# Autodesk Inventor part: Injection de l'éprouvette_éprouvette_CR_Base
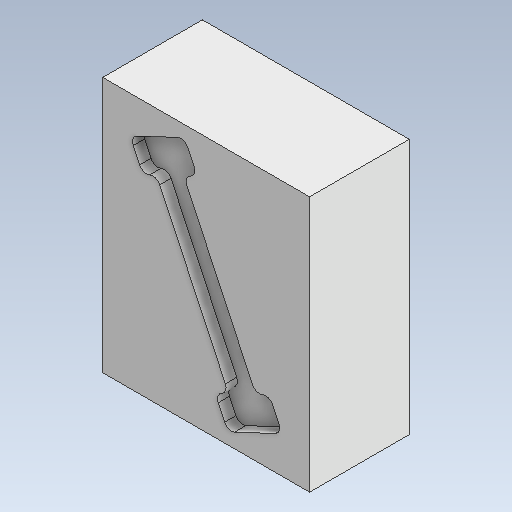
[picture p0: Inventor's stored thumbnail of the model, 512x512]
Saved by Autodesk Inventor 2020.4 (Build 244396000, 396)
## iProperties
Created: 2021-10
Part Number: Injection de l'éprouvette_éprouvette_CR_Base
Material: Générique
Document SubType Name: Modeling
Designer: mel
Density: 1 g/cm^3
Appearance: Par défaut
Author: mel
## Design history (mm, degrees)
node "Injection de l'éprouvette_éprouvette_MP"
feature "Solide6::Injection de l'éprouvette_éprouvette_MP"
tag "FonctionRepérage2"
node "Solide2"
feature "Injection de l'éprouvette_éprouvette_MP_Corps"
